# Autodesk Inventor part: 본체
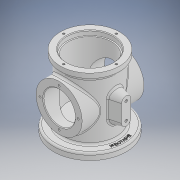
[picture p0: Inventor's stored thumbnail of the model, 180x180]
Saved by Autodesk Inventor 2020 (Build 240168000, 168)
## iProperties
Created: 2023-02
Part Number: 본체
Material: 일반
Document SubType Name: Modeling
Designer: com
Density: 1 g/cm^3
Appearance: 기본값
Mass: 287.411 g
Surface Area: 759.773 cm^2
Volume: 287.411 cm^3
Author: com
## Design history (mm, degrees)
sketch "스케치1"
  geometry: C1 r 55 at (0, 0); 1 further point
  constraints: 1 centre point, 1 coincident
  dimensions: "d0" = 110 diameter of C1
extrude "돌출1" new body sketch "스케치1" distance "d1" = 10; taper "d2" = 0 deg
sketch "스케치2"
  geometry: C1 r 40 at (0, 0); 1 further point
  constraints: 1 centre point, 1 coincident
  dimensions: "d3" = 80 diameter of C1
extrude "돌출2" join sketch "스케치2" distance "d4" = 98; taper "d5" = 0 deg
sketch "스케치3"
  geometry: C1 r 45 at (0, 0); 1 further point
  constraints: 1 centre point, 1 coincident
  dimensions: "d6" = 90 diameter of C1
extrude "돌출3" join sketch "스케치3" distance "d7" = 10; taper "d8" = 0 deg
sketch "스케치4"
  geometry: C1 r 35 at (0, 0); 1 further point
  constraints: 1 centre point, 1 coincident
  dimensions: "d9" = 70 diameter of C1
extrude "돌출4" cut sketch "스케치4" distance "d10" = 7; taper "d11" = 0 deg
sketch "스케치5"
  geometry: C1 r 33 at (0, 0); 1 further point
  constraints: 1 centre point, 1 coincident
  dimensions: "d12" = 66 diameter of C1
extrude "돌출5" cut sketch "스케치5" distance "d13" = 79; taper "d14" = 0 deg
sketch "스케치6"
  geometry: C1 r 33 at (0, 0); 1 further point
  constraints: 1 centre point, 1 coincident
  dimensions: "d15" = 66 diameter of C1
extrude "돌출6" cut sketch "스케치6" distance "d16" = 16; taper "d17" = 0 deg
sketch "스케치7"
  geometry: C1 r 5 at (0, 0); 1 further point
  constraints: 1 centre point, 1 coincident
  dimensions: "d18" = 10 diameter of C1
extrude "돌출7" cut sketch "스케치7" stored distance "d19" = 16; taper "d20" = 0 deg
node "작업 평면1"
sketch "스케치8"
  geometry: L1 (55, 0)-(-55, 0) reference; C1 r 35 at (0, 54); 2 further points
  constraints: 1 centre point, 1 midpoint, 1 vertical alignment
  dimensions: "d22" = 70 diameter of C1; "d23" = 54 distance from line of L1 C1.centre
extrude "돌출8" join sketch "스케치8" stored distance "d24" = 16; taper "d25" = 0 deg; dims "d9" = 70
sketch "스케치9"
  geometry: C1 r 24 at (0, 0); 1 further point
  constraints: 1 centre point
  dimensions: "d26" = 48 diameter of C1
extrude "돌출9" cut sketch "스케치9" extent not by distance; stored distance "d27" = 0; taper "d28" = 0 deg
sketch "스케치10" dims "d29" = 58
  geometry: C1 r 35 at (0, 0) reference; 3 further points
  constraints: 1 vertical alignment, 3 other
hole "구멍1" sketch "스케치10" at (0, 29) diameter "d30" = 3.242; stored, may be unused: countersink angle "d34" = 90 deg, drill point angle "d36" = 118 deg; dims "d31" = 6, "d32" = 4, "d33" = 2, "d35" = 8
sketch "스케치11"
  geometry: C1 r 40 at (0, 0); 3 further points
  constraints: 1 centre point, 1 coincident, 1 horizontal alignment, 1 other
  dimensions: "d40" = 80 diameter of C1
hole "구멍2" sketch "스케치11" at (40, 0) diameter "d41" = 3.242; stored, may be unused: countersink angle "d45" = 90 deg, drill point angle "d47" = 118 deg; dims "d42" = 6, "d43" = 4, "d44" = 2, "d46" = 8
node "작업 평면2"
sketch "스케치12"
  geometry: L1 (74, 0)-(34, 0); L2 (67, 7)-(41, 7); L3 (41, -7)-(67, -7); L4 (89, 47)-(19, 47) reference; L5 (89, 47)-(19, 47); L6 (19, 47)-(19, 40) reference; A1 r 7 centre (67, 0) between (67, -7) and (67, 7); A2 r 7 centre (41, 0) between (41, 7) and (41, -7); 3 further points
  constraints: 10 end point, 6 point on circle, 4 tangent, 3 point on line, 2 centre point, 2 horizontal, 2 midpoint, 1 horizontal alignment, 1 parallel, 1 vertical alignment
  dimensions: "d52" = 40 distance of L1.start L1.end; "d53" = 14 diameter of A2
extrude "돌출10" join sketch "스케치12" stored distance "d54" = 16; taper "d55" = 15 deg; dims "d9" = 70
sketch "스케치13"
  geometry: A1 r 7 centre (0, 67) between (7, 67) and (-7, 67) reference; A2 r 7 centre (0, 41) between (-7, 41) and (7, 41) reference; 3 further points
  constraints: 2 coincident
hole "구멍3" sketch "스케치13" at (0, 67), (0, 41) diameter "d56" = 4.134; stored, may be unused: countersink angle "d60" = 90 deg, drill point angle "d62" = 118 deg; dims "d57" = 6, "d58" = 4, "d59" = 2, "d61" = 8
fillet "모깎기1" dims "d63" = 3
chamfer "모따기1" distance "d64" = 1; stored, may be unused: second distance "d65" = 2, angle "d66" = 45 deg
sketch "스케치14"
  geometry: C1 r 50 at (0, 0); 1 further point
  constraints: 1 centre point, 1 coincident, 1 other
  dimensions: "d67" = 100 diameter of C1
feature "엠보싱1" sketch "스케치14" dims "d68" = 0.5, "d69" = 0
node "솔리드1"
mirror "미러1"
pattern_circular "원형 패턴1" dims angle "d38" = 360 deg
mirror "미러2"
pattern_circular "원형 패턴2" dims angle "d49" = 360 deg
feature "A9D066F2-1C7D-4E18-AEED-F7BC21143FA4" dims "d30" = 3.242, "d31" = 6, "d32" = 4, "d33" = 2, "d34" = 90 deg, "d35" = 8, "d36" = 118 deg
other parameters: "d21" = 47, "d51" = 55
